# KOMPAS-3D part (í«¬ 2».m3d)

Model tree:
1. Эскиз:1
2. Операция выдавливания:1
     Расстояние 1 = 3
3. Эскиз:2
4. Операция выдавливания:2
     Расстояние 1 = 78
5. Эскиз:3
6. Операция выдавливания:3
     Расстояние 1 = 3
7. Эскиз:4
8. Операция выдавливания:4
     Расстояние 1 = 4
9. Эскиз:5
10. Операция выдавливания:5
     Расстояние 1 = 4
11. Эскиз:6
12. Вырезать элемент выдавливания:1
     Расстояние 2 = 110; Расстояние 1 = 100
